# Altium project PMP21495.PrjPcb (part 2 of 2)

## Sheet PowerStage.SchDoc
size 431 x 279 mm; Date: Not shown in title block; ApprovedBy: Not shown in title block; CheckedBy: Not shown in title block; Author: Not shown in title block; CompanyName: Not shown in title block; Engineer: Not shown in title block; Organization: Not shown in title block; Address1: Not shown in title block; Address2: Not shown in title block; Address3: Not shown in title block; Address4: Not shown in title block; DocumentNumber: 1; Revision: Use project parameter SCH_Rev; SheetNumber: 1; SheetTotal: 2; PageSetup: Record=PageOptions¦CenterHorizontal=True¦CenterVertical=True¦PrintScale=1.00¦XCorrection=1.00¦YCorrection=1.00¦PrintKind=0¦BorderSize=5000000¦LeftOffset=0¦BottomOffset=0¦Orientation=2¦PaperLength=1000¦PaperWidth=1000¦Scale=100¦PaperSource=15¦PrintQuality=600¦MediaType=1¦DitherType=10¦PaperKind=Letter¦PrintScaleMode=1
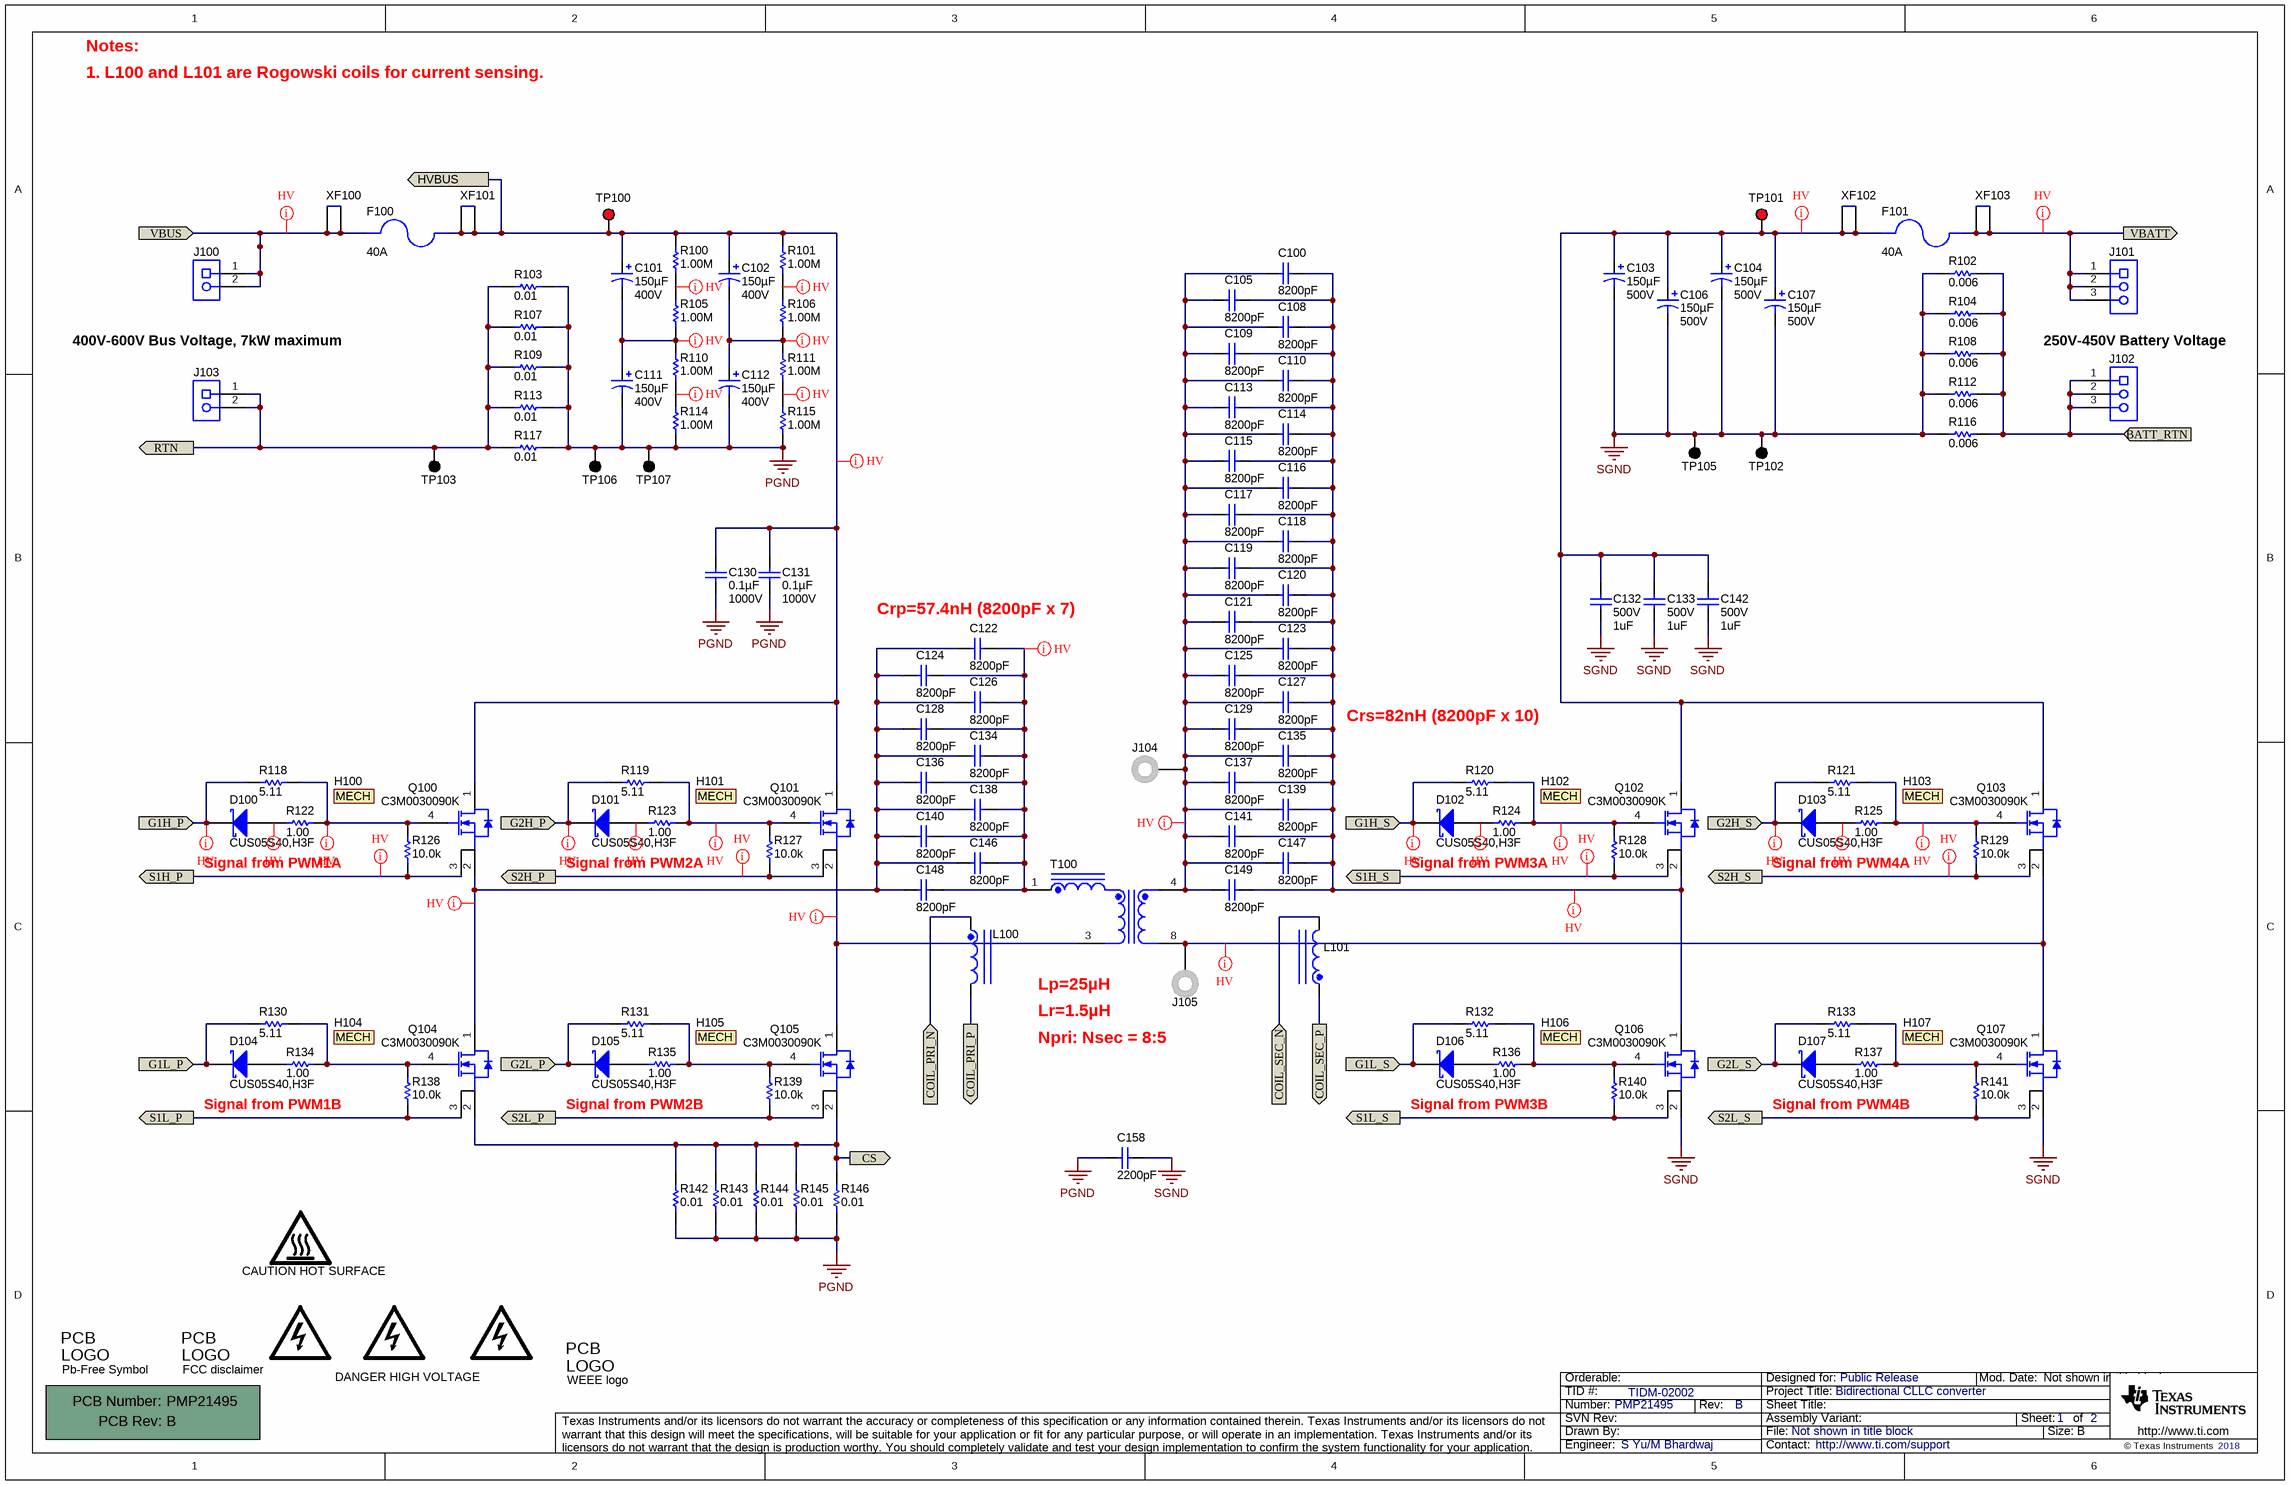
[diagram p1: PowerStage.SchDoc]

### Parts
!PCB100  Printed Circuit Board  (value not drawn)  (mechanical)
C100  ValueDisplayed: 8200pF  [1206_190]
C101  ValueDisplayed: 150µF  Value2: 400V  [FC_1600x4000]  (hidden comment: 400BXW150MEFC16X45)
C102  ValueDisplayed: 150µF  Value2: 400V  [FC_1600x4000]  (hidden comment: 400BXW150MEFC16X45)
C103  ValueDisplayed: 150µF  Value2: 500V  [Nichicon_2200x4500_Snap]  (hidden comment: 500MXG150MEFCSN22X55)
C104  ValueDisplayed: 150µF  Value2: 500V  [Nichicon_2200x4500_Snap]  (hidden comment: 500MXG150MEFCSN22X55)
C105  ValueDisplayed: 8200pF  [1206_190]
C106  ValueDisplayed: 150µF  Value2: 500V  [Nichicon_2200x4500_Snap]  (hidden comment: 500MXG150MEFCSN22X55)
C107  ValueDisplayed: 150µF  Value2: 500V  [Nichicon_2200x4500_Snap]  (hidden comment: 500MXG150MEFCSN22X55)
C108  ValueDisplayed: 8200pF  [1206_190]
C109  ValueDisplayed: 8200pF  [1206_190]
C110  ValueDisplayed: 8200pF  [1206_190]
C111  ValueDisplayed: 150µF  Value2: 400V  [FC_1600x4000]  (hidden comment: 400BXW150MEFC16X45)
C112  ValueDisplayed: 150µF  Value2: 400V  [FC_1600x4000]  (hidden comment: 400BXW150MEFC16X45)
C113  ValueDisplayed: 8200pF  [1206_190]
C114  ValueDisplayed: 8200pF  [1206_190]
C115  ValueDisplayed: 8200pF  [1206_190]
C116  ValueDisplayed: 8200pF  [1206_190]
C117  ValueDisplayed: 8200pF  [1206_190]
C118  ValueDisplayed: 8200pF  [1206_190]
C119  ValueDisplayed: 8200pF  [1206_190]
C120  ValueDisplayed: 8200pF  [1206_190]
C121  ValueDisplayed: 8200pF  [1206_190]
C122  ValueDisplayed: 8200pF  [1206_190]
C123  ValueDisplayed: 8200pF  [1206_190]
C124  ValueDisplayed: 8200pF  [1206_190]
C125  ValueDisplayed: 8200pF  [1206_190]
C126  ValueDisplayed: 8200pF  [1206_190]
C127  ValueDisplayed: 8200pF  [1206_190]
C128  ValueDisplayed: 8200pF  [1206_190]
C129  ValueDisplayed: 8200pF  [1206_190]
C130  ValueDisplayed: 0.1µF  Value2: 1000V  [1812_254]  (hidden comment: 1812Y1K00104KXT)
C131  ValueDisplayed: 0.1µF  Value2: 1000V  [1812_254]  (hidden comment: 1812Y1K00104KXT)
C132  VDC_V: 500V  ValueDisplayed: 1uF  [B58031I_1084x785x450]  (hidden comment: B58031I5105M002)
C133  VDC_V: 500V  ValueDisplayed: 1uF  [B58031I_1084x785x450]  (hidden comment: B58031I5105M002)
C134  ValueDisplayed: 8200pF  [1206_190]
C135  ValueDisplayed: 8200pF  [1206_190]
C136  ValueDisplayed: 8200pF  [1206_190]
C137  ValueDisplayed: 8200pF  [1206_190]
C138  ValueDisplayed: 8200pF  [1206_190]
C139  ValueDisplayed: 8200pF  [1206_190]
C140  ValueDisplayed: 8200pF  [1206_190]
C141  ValueDisplayed: 8200pF  [1206_190]
C142  VDC_V: 500V  ValueDisplayed: 1uF  [B58031I_1084x785x450]  (hidden comment: B58031I5105M002)
C146  ValueDisplayed: 8200pF  [1206_190]
C147  ValueDisplayed: 8200pF  [1206_190]
C148  ValueDisplayed: 8200pF  [1206_190]
C149  ValueDisplayed: 8200pF  [1206_190]
C158  ValueDisplayed: 2200pF  [CAPRD1000W60D900H1200]  (hidden comment: DE1E3KX222MA4BL01)
D100  CUS05S40,H3F  [SOD-323]
D101  CUS05S40,H3F  [SOD-323]
D102  CUS05S40,H3F  [SOD-323]
D103  CUS05S40,H3F  [SOD-323]
D104  CUS05S40,H3F  [SOD-323]
D105  CUS05S40,H3F  [SOD-323]
D106  CUS05S40,H3F  [SOD-323]
D107  CUS05S40,H3F  [SOD-323]
F100  Irating_A: 40A  (hidden comment: SC-40)  (mechanical)
F101  Irating_A: 40A  (hidden comment: SC-40)  (mechanical)
H100  (no value)  (mechanical)
H101  (no value)  (mechanical)
H102  (no value)  (mechanical)
H103  (no value)  (mechanical)
H104  (no value)  (mechanical)
H105  (no value)  (mechanical)
H106  (no value)  (mechanical)
H107  (no value)  (mechanical)
J100  282856-2  [TE_282856-2]  (value not drawn)
J101  282856-3  [TE_282856-3]  (value not drawn)
J102  282856-3  [TE_282856-3]  (value not drawn)
J103  282856-2  [TE_282856-2]  (value not drawn)
J104  575-4  [Keystone_575-4]  (value not drawn)
J105  575-4  [Keystone_575-4]  (value not drawn)
L100  RLTI-1310  [RLTI-1310]  (value not drawn)
L101  RLTI-1310  [RLTI-1310]  (value not drawn)
Logo2  Pb-Free Symbol  [Pb-Free_Overlay_Medium]  (no BOM)
Logo3  FCC disclaimer  [FCC_disclaimer]  (no BOM)
Logo4  WEEE logo  [WEEE_Minimum]  (no BOM)
LOGO100  CAUTION HOT SURFACE  [IEC_HotSurface_Medium]  (no BOM)
LOGO101  DANGER HIGH VOLTAGE  [IEC_HighVoltage_Medium]  (value not drawn)  (no BOM)
LOGO102  DANGER HIGH VOLTAGE  [IEC_HighVoltage_Medium]  (no BOM)
LOGO104  DANGER HIGH VOLTAGE  [IEC_HighVoltage_Medium]  (value not drawn)  (no BOM)
Q100  C3M0030090K  [TO-247-4]
Q101  C3M0030090K  [TO-247-4]
Q102  C3M0030090K  [TO-247-4]
Q103  C3M0030090K  [TO-247-4]
Q104  C3M0030090K  [TO-247-4]
Q105  C3M0030090K  [TO-247-4]
Q106  C3M0030090K  [TO-247-4]
Q107  C3M0030090K  [TO-247-4]
R100  ValueDisplayed: 1.00M  [1206]  (hidden comment: CRCW12061M00FKEA)
R101  ValueDisplayed: 1.00M  [1206]  (hidden comment: CRCW12061M00FKEA)
R102  ValueDisplayed: 0.006  [CSNL1206]  (hidden comment: PMR18EZPFU6L00)
R103  ValueDisplayed: 0.01  [1206]  (hidden comment: WSLP1206R0100FEA)
R104  ValueDisplayed: 0.006  [CSNL1206]  (hidden comment: PMR18EZPFU6L00)
R105  ValueDisplayed: 1.00M  [1206]  (hidden comment: CRCW12061M00FKEA)
R106  ValueDisplayed: 1.00M  [1206]  (hidden comment: CRCW12061M00FKEA)
R107  ValueDisplayed: 0.01  [1206]  (hidden comment: WSLP1206R0100FEA)
R108  ValueDisplayed: 0.006  [CSNL1206]  (hidden comment: PMR18EZPFU6L00)
R109  ValueDisplayed: 0.01  [1206]  (hidden comment: WSLP1206R0100FEA)
R110  ValueDisplayed: 1.00M  [1206]  (hidden comment: CRCW12061M00FKEA)
R111  ValueDisplayed: 1.00M  [1206]  (hidden comment: CRCW12061M00FKEA)
R112  ValueDisplayed: 0.006  [CSNL1206]  (hidden comment: PMR18EZPFU6L00)
R113  ValueDisplayed: 0.01  [1206]  (hidden comment: WSLP1206R0100FEA)
R114  ValueDisplayed: 1.00M  [1206]  (hidden comment: CRCW12061M00FKEA)
R115  ValueDisplayed: 1.00M  [1206]  (hidden comment: CRCW12061M00FKEA)
R116  ValueDisplayed: 0.006  [CSNL1206]  (hidden comment: PMR18EZPFU6L00)
R117  ValueDisplayed: 0.01  [1206]  (hidden comment: WSLP1206R0100FEA)
R118  ValueDisplayed: 5.11  [0603]  (hidden comment: CRCW06035R11FKEA)
R119  ValueDisplayed: 5.11  [0603]  (hidden comment: CRCW06035R11FKEA)
R120  ValueDisplayed: 5.11  [0603]  (hidden comment: CRCW06035R11FKEA)
R121  ValueDisplayed: 5.11  [0603]  (hidden comment: CRCW06035R11FKEA)
R122  ValueDisplayed: 1.00  [0603]  (hidden comment: RC0603FR-071RL)
R123  ValueDisplayed: 1.00  [0603]  (hidden comment: RC0603FR-071RL)
R124  ValueDisplayed: 1.00  [0603]  (hidden comment: RC0603FR-071RL)
R125  ValueDisplayed: 1.00  [0603]  (hidden comment: RC0603FR-071RL)
R126  ValueDisplayed: 10.0k  [0603]  (hidden comment: CRCW060310K0FKEA)
R127  ValueDisplayed: 10.0k  [0603]  (hidden comment: CRCW060310K0FKEA)
R128  ValueDisplayed: 10.0k  [0603]  (hidden comment: CRCW060310K0FKEA)
R129  ValueDisplayed: 10.0k  [0603]  (hidden comment: CRCW060310K0FKEA)
R130  ValueDisplayed: 5.11  [0603]  (hidden comment: CRCW06035R11FKEA)
R131  ValueDisplayed: 5.11  [0603]  (hidden comment: CRCW06035R11FKEA)
R132  ValueDisplayed: 5.11  [0603]  (hidden comment: CRCW06035R11FKEA)
R133  ValueDisplayed: 5.11  [0603]  (hidden comment: CRCW06035R11FKEA)
R134  ValueDisplayed: 1.00  [0603]  (hidden comment: RC0603FR-071RL)
R135  ValueDisplayed: 1.00  [0603]  (hidden comment: RC0603FR-071RL)
R136  ValueDisplayed: 1.00  [0603]  (hidden comment: RC0603FR-071RL)
R137  ValueDisplayed: 1.00  [0603]  (hidden comment: RC0603FR-071RL)
R138  ValueDisplayed: 10.0k  [0603]  (hidden comment: CRCW060310K0FKEA)
R139  ValueDisplayed: 10.0k  [0603]  (hidden comment: CRCW060310K0FKEA)
R140  ValueDisplayed: 10.0k  [0603]  (hidden comment: CRCW060310K0FKEA)
R141  ValueDisplayed: 10.0k  [0603]  (hidden comment: CRCW060310K0FKEA)
R142  ValueDisplayed: 0.01  [1206]  (hidden comment: WSLP1206R0100FEA)
R143  ValueDisplayed: 0.01  [1206]  (hidden comment: WSLP1206R0100FEA)
R144  ValueDisplayed: 0.01  [1206]  (hidden comment: WSLP1206R0100FEA)
R145  ValueDisplayed: 0.01  [1206]  (hidden comment: WSLP1206R0100FEA)
R146  ValueDisplayed: 0.01  [1206]  (hidden comment: WSLP1206R0100FEA)
T100  (no value)  [Payton_60518]
TP100  5000  [Keystone5000]  (value not drawn)
TP101  5000  [Keystone5000]  (value not drawn)
TP102  5001  [Keystone5001]  (value not drawn)
TP103  5001  [Keystone5001]  (value not drawn)
TP105  5001  [Keystone5001]  (value not drawn)
TP106  5001  [Keystone5001]  (value not drawn)
TP107  5001  [Keystone5001]  (value not drawn)
XF100  1A3400-10  [Eaton_1A3400-10]  (value not drawn)
XF101  1A3400-10  [Eaton_1A3400-10]  (value not drawn)
XF102  1A3400-10  [Eaton_1A3400-10]  (value not drawn)
XF103  1A3400-10  [Eaton_1A3400-10]  (value not drawn)

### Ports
BATT_RTN, COIL_PRI_N, COIL_PRI_P (out), COIL_SEC_N, COIL_SEC_P (out), CS (out), G1H_P (in), G1H_S (in), G1L_P (in), G1L_S (in), G2H_P (in), G2H_S (in), G2L_P (in), G2L_S (in), HVBUS, RTN (out), S1H_P, S1H_S, S1L_P, S1L_S, S2H_P, S2H_S, S2L_P, S2L_S, VBATT (out), VBUS (in)

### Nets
PGND: C111.2(-) C112.2(-) C130.2 C131.2 C158.2 R103.1 R107.1 R109.1 R113.1 R114.1 R115.1 R117.1 R142.1 R143.1 R144.1 R145.1 R146.1 TP106.1 TP107.1
SGND: C103.2(-) C104.2(-) C106.2(-) C107.2(-) C132.2 C133.2 C142.2 C158.1 Q106.2(S) Q107.2(S) R102.2 R104.2 R108.2 R112.2 R116.2 TP102.1 TP105.1
BATT_RTN: J102.1 J102.2 J102.3 R102.1 R104.1 R108.1 R112.1 R116.1 ; port BATT_RTN
COIL_PRI_N: L100.1 ; port COIL_PRI_N
COIL_PRI_P: L100.2 ; port COIL_PRI_P
COIL_SEC_N: L101.2 ; port COIL_SEC_N
COIL_SEC_P: L101.1 ; port COIL_SEC_P
CS: Q104.2(S) Q105.2(S) R142.2 R143.2 R144.2 R145.2 R146.2 ; port CS
G1H_P: D100.1(K) R118.1 ; port G1H_P
G1H_S: D102.1(K) R120.1 ; port G1H_S
G1L_P: D104.1(K) R130.1 ; port G1L_P
G1L_S: D106.1(K) R132.1 ; port G1L_S
G2H_P: D101.1(K) R119.1 ; port G2H_P
G2H_S: D103.1(K) R121.1 ; port G2H_S
G2L_P: D105.1(K) R131.1 ; port G2L_P
G2L_S: D107.1(K) R133.1 ; port G2L_S
HVBUS: C101.1(+) C102.1(+) C130.1 C131.1 Q100.1(D) Q101.1(D) R100.2 R101.2 TP100.1 XF101.1 XF101.2 ; port HVBUS
RTN: J103.1 J103.2 R103.2 R107.2 R109.2 R113.2 R117.2 TP103.1 ; port RTN
S1H_P: Q100.3(KS) R126.1 ; port S1H_P
S1H_S: Q102.3(KS) R128.1 ; port S1H_S
S1L_P: Q104.3(KS) R138.1 ; port S1L_P
S1L_S: Q106.3(KS) R140.1 ; port S1L_S
S2H_P: Q101.3(KS) R127.1 ; port S2H_P
S2H_S: Q103.3(KS) R129.1 ; port S2H_S
S2L_P: Q105.3(KS) R139.1 ; port S2L_P
S2L_S: Q107.3(KS) R141.1 ; port S2L_S
VBATT: J101.1 J101.2 J101.3 XF103.1 XF103.2 ; port VBATT
VBUS: J100.1 J100.2 XF100.1 XF100.2 ; port VBUS
NetC100_1: C100.1 C105.1 C108.1 C109.1 C110.1 C113.1 C114.1 C115.1 C116.1 C117.1 C118.1 C119.1 C120.1 C121.1 C123.1 C125.1 C127.1 C129.1 C135.1 C137.1 C139.1 C141.1 C147.1 C149.1 Q102.2(S) Q106.1(D)
NetC100_2: C100.2 C105.2 C108.2 C109.2 C110.2 C113.2 C114.2 C115.2 C116.2 C117.2 C118.2 C119.2 C120.2 C121.2 C123.2 C125.2 C127.2 C129.2 C135.2 C137.2 C139.2 C141.2 C147.2 C149.2 J104.1 T100.4
NetC101_2: C101.2(-) C111.1(+) R105.1 R110.2
NetC102_2: C102.2(-) C112.1(+) R106.1 R111.2
NetC103_1: C103.1(+) C104.1(+) C106.1(+) C107.1(+) C132.1 C133.1 C142.1 Q102.1(D) Q103.1(D) TP101.1 XF102.1 XF102.2
NetC122_1: C122.1 C124.1 C126.1 C128.1 C134.1 C136.1 C138.1 C140.1 C146.1 C148.1 T100.1
NetC122_2: C122.2 C124.2 C126.2 C128.2 C134.2 C136.2 C138.2 C140.2 C146.2 C148.2 Q100.2(S) Q104.1(D)
NetD100_2: D100.2(A) R122.1
NetD101_2: D101.2(A) R123.1
NetD102_2: D102.2(A) R124.1
NetD103_2: D103.2(A) R125.1
NetD104_2: D104.2(A) R134.1
NetD105_2: D105.2(A) R135.1
NetD106_2: D106.2(A) R136.1
NetD107_2: D107.2(A) R137.1
NetJ105_1: J105.1 Q103.2(S) Q107.1(D) T100.8
NetQ100_4: Q100.4(G) R118.2 R122.2 R126.2
NetQ101_2: Q101.2(S) Q105.1(D) T100.3
NetQ101_4: Q101.4(G) R119.2 R123.2 R127.2
NetQ102_4: Q102.4(G) R120.2 R124.2 R128.2
NetQ103_4: Q103.4(G) R121.2 R125.2 R129.2
NetQ104_4: Q104.4(G) R130.2 R134.2 R138.2
NetQ105_4: Q105.4(G) R131.2 R135.2 R139.2
NetQ106_4: Q106.4(G) R132.2 R136.2 R140.2
NetQ107_4: Q107.4(G) R133.2 R137.2 R141.2
NetR100_1: R100.1 R105.2
NetR101_1: R101.1 R106.2
NetR110_1: R110.1 R114.2
NetR111_1: R111.1 R115.2

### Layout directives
net class HV: G1H_P, G1H_S, G2H_P, G2H_S, HVBUS, NetC100_1, NetC100_2, NetC101_2, NetC102_2, NetC103_1, NetC122_1, NetC122_2, NetD100_2, NetD101_2, NetD102_2, NetD103_2, NetJ105_1, NetQ100_4, NetQ101_2, NetQ101_4, NetQ102_4, NetQ103_4, NetR100_1, NetR101_1, NetR110_1, NetR111_1, S1H_P, S1H_S, S2H_P, S2H_S, VBATT, VBUS

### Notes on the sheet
- Notes:
- 1. L100 and L101 are Rogowski coils for current sensing.
- 400V-600V Bus Voltage, 7kW maximum
- 250V-450V Battery Voltage
- (near C122) Crp=57.4nH (8200pF x 7)
- Crs=82nH (8200pF x 10)
- Signal from PWM1A
- Signal from PWM2A
- Signal from PWM3A
- Signal from PWM4A
- (near T100) Lp=25µH
- Lr=1.5µH
- Npri: Nsec = 8:5
- Signal from PWM1B
- Signal from PWM2B
- Signal from PWM3B
- Signal from PWM4B

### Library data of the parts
!PCB100 = CMP-0003618-2: Manufacturer: Any; PartNumber: PMP21495
C100 C105 C108-C110 C113-C129 C134-C141 C146-C149 = CMP-0008795-2: CAP CER 8200PF 630V NP0 1206; Manufacturer: TDK; PartNumber: CGA5L4NP02J822J160AA; TaMin_C: -55°C; Polarized: N; TempCo: C0G; SizeAreaWB_mm2: 10.92; Value1: Unknown; U/M: EA; TaMax_C: 125°C; Tolerance_%: 5%; SizeZ_mm: 1.9; SizeX_mm: 3.2; SizeY_mm: 1.6; Cap_Case: 1206; SizeArea_mm2: 5.12; CompType: Capacitor; AEC Qualified: Y; Cap_F: 100nF; AEC Grade: 1; AEC Category: Q200
C101 C102 C111 C112 = EEU-FC2A471: CAP ALUM 150UF 20% 400V RADIAL; Manufacturer: Rubycon; Polarized: Y; CompType: Capacitor; U/M: EA; Tolerance_%: 20; VDC_V: 400; ESR_ohm: 0.047; IRMS_A: 1.92; TaMin_C: -55; TaMax_C: 105; Cap_Case: 16x40mm; SizeAreaWB_mm2: 324; SizeArea_mm2: 256; SizeX_mm: 16; SizeZ_mm: 42; AEC Category: Q200; AEC Grade: 2; Green_Lifecycle: Active; Green_REACh: Passed
C103 C104 C106 C107 = LLS2G221MELZ: CAP ALUM 150UF 20% 500V SNAP; Manufacturer: Rubycon; Polarized: Y; CompType: Capacitor; U/M: EA; Cap_F: 0.00022; Tolerance_%: 20; VDC_V: 500; IRMS_A: 1.58; Cap_Case: 22x45mm; SizeAreaWB_mm2: 576; SizeArea_mm2: 484; SizeX_mm: 22; SizeZ_mm: 47; AEC Category: Q200; AEC Qualified: N
C130 = C1812W104KDRACTU: CAP, CERM, 0.1 µF, 1000 V,+/- 10%, X7R, 1812; Manufacturer: Knowles Syfer; Polarized: N; CompType: Capacitor; Value: 0.1uF; U/M: EA; Cap_F: 0.0000001; Tolerance_%: 10; VDC_V: 1000; TaMin_C: -55; TaMax_C: 125; Cap_Case: 1812; SizeArea_mm2: 14.4; SizeAreaWB_mm2: 23.1; SizeX_mm: 4.5; SizeY_mm: 3.2; SizeZ_mm: 2.54; AEC Category: Q200; Green_Lifecycle: Active; Green_REACh: Passed
C131 = C1812W104KDRACTU: CAP CER 0.1UF 1KV X7R 1812; Manufacturer: Knowles Syfer; Polarized: N; CompType: Capacitor; U/M: EA; Cap_F: 0.0000001; Tolerance_%: 10; VDC_V: 1000; TaMin_C: -55; TaMax_C: 125; Cap_Case: 1812; SizeArea_mm2: 14.4; SizeAreaWB_mm2: 23.1; SizeX_mm: 4.5; SizeY_mm: 3.2; SizeZ_mm: 2.54; AEC Category: Q200; Green_Lifecycle: Active; Green_REACh: Passed
C132 C133 C142 = CMP-0009311-2: CAP, CERM, 1 uF, 500 V, +/- 20%, B58031, AEC-Q200 Grade 0, 6.84x7.85mm; Manufacturer: TDK; PartNumber: B58031I5105M062; TaMin_C: -40°C; Polarized: N; SizeAreaWB_mm2: 126.474; Value1: Unknown; U/M: EA; Value: 1uF; TaMax_C: 150°C; SizeZ_mm: 4.5; SizeX_mm: 10.84; SizeY_mm: 7.85; Cap_Case: 10.84x7.85x4.5mm; SizeArea_mm2: 85.094; CompType: Capacitor; AEC Qualified: Y; Cap_F: 1µF; IRMS_A: 7.5A; AEC Grade: 0; AEC Category: Q200
C158 = DE1E3KX222MA4BL01: CAP, CERM, 2200 pF, 250 V, +/- 20%, E, Cap, 7x12x9 mm; Manufacturer: MuRata; Polarized: N; CompType: Capacitor; Value: 2200pF; U/M: EA; Cap_F: 0.0000000022; Tolerance_%: 20; Value1: Unknown; VDC_V: 250; Value2: 250V; TaMin_C: -25; TaMax_C: 85
D100-D107 = CUS05S40,H3F: Diode, Schottky, 40 V, 0.5 A, SOD-323; Manufacturer: Toshiba; U/M: EA; Vf_V: 0.6; Value: 40V; Value1: 0.5A; Value2: 0.6V; Io_A: 0.5; Vr_V: 40; TJmax_C: 125; SizeAreaWB_mm2: 8.695; SizeArea_mm2: 3.645; SizeX_mm: 2.7; SizeY_mm: 1.35; SizeZ_mm: 1; AEC Category: Q101; AEC Qualified: N; Green_Lifecycle: Not Set; Green_REACh: Incomplete
F100 F101 = CMP-0082087-1: Fuse, 40 A, 480 VAC, 300 VDC, Holder; Manufacturer: Eaton; Fuse Speed: Slow; Fuse Technology: Cartridge; VAC_V: 480V; Interrupt_AC: 100kA; VDC_V: 300V; Interrupt_DC: 10kA
H100-H107 = CMP-0082086-1: THERM PAD 21.84MMX18.8MM PINK; Manufacturer: Bergquist; PartNumber: SP900S-0.009-00-90; CompType: Thermal Pad
J100 J103 = CMP-0054978-1: Therminal Block, 5 mm, 2-pole, Tin, TH; Manufacturer: TE Connectivity; CT: TRUE; CompType: Terminal Block; CNHeader: FALSE
J101 J102 = CMP-0054983-1: Receptacle, 3x1, 5mm, R/A, TH; Manufacturer: TE Connectivity; CNHeader: FALSE; Current_A: 24A; Gender: Female; Voltage_V: 300V; CompType: Terminal Block; Row_Count: 1; Pitch_mm: 5; ContactFinish: Tin; CT: TRUE; Cert_UL: Y
J104 J105 = CMP-0055165-2: Standard Banana Jack, Uninsulated, 5.5mm; Manufacturer: Keystone; CT: TRUE; Green_REACh: Passed; CNHeader: FALSE; Green_Lifecycle: Active
L100 L101 = CMP-0086080-1: Inductor, Toroid, 7 µH, 1.155 ohm, TH; Manufacturer: Renco Electronics; SizeZ_mm: 18.669; SizeAreaWB_mm2: 135.836668; SizeX_mm: 4.572; AEC Qualified: N; AEC Category: Q200; Ind_H: 7µH; DCR_ohm: 1.155; Value: 7uH; Value2: A; SizeArea_mm2: 85.354668
Logo2 = CMP-0074839-1: SymbolCreator: a0412235; Library Reference: Logo
Logo3 = CMP-0074847-1: FCC_disclaimer; Library Reference: Logo
Logo4 = CMP-0074769-1
LOGO100 = IEC_HotSurface: IEC 61010-1 Hot Surface Warning; SymbolCreator: a0412235
LOGO101 LOGO102 LOGO104 = IEC_HighVoltage: IEC 61010-1 High Voltage Warning; SymbolCreator: a0412235
Q100-Q107 = CMP-0067575-2: ZFET 900V, 30 MOHM, G3 SIC MOSFE; Manufacturer: Cree; Alternate Manufacturer: None; CompType: MOSFET; AEC Qualified: N; AEC Category: Q101; U/M: EA
R100 R101 R105 R106 R110 R111 R114 R115 = CRCW12061M00FKEA: RES, 1.00 M, 1%, 0.25 W, 1206; Manufacturer: Vishay-Dale; CompType: Resistor; Value: 1.00Meg; Res_ohm: 1000000; Value_Code: 1M00; Tolerance_%: 1; Power_W: 0.25; Value2: 0.25W; VDC_V: 200; TempCo: 100 ppm/C; SizeArea_mm2: 5.12; SizeX_mm: 3.2; SizeY_mm: 1.6; SizeZ_mm: 1.35; EIA_Code: E96; U/M: EA; AEC Category: Q200; Green_Lifecycle: Active; Green_REACh: Passed
R102 R104 R108 R112 R116 = CSNL1206FT5L00: RES 0.006 OHM 1% 1W 1206; Manufacturer: Rohm Semiconductor; CompType: Resistor; Value: 0.006; Tolerance_%: 1; TempCo: 50 ppm/C; SizeArea_mm2: 5.12; SizeX_mm: 3.2; SizeY_mm: 1.6; SizeZ_mm: 0.9; EIA_Code: E96; U/M: EA; AEC Category: Q200; AEC Qualified: N
R103 R107 R109 R113 R117 R142-R146 = CMP-0018570-2: RES, 0.01, 1%, 1 W, 1206; Manufacturer: Vishay-Dale; Power_W: 1W; TempCo: 75 ppm/C; Value_Code: R010; U/M: EA; Value: 0.01; EIA_Code: E96; SizeX_mm: 3.2; SizeY_mm: 1.6; SizeZ_mm: 1.35; SizeArea_mm2: 5.12; CompType: Resistor; AEC Category: Q200
R118-R121 R130-R133 = CRCW06035R11FKEA: RES, 5.11, 1%, 0.1 W, 0603; Manufacturer: Vishay-Dale; CompType: Resistor; Value: 5.11; Value_Code: 5R11; Tolerance_%: 1; Power_W: 0.1; Value2: 0.1W; VDC_V: 75; TempCo: 100 ppm/C; SizeArea_mm2: 1.28; SizeX_mm: 1.6; SizeY_mm: 0.8; EIA_Code: E96; U/M: EA; AEC Category: Q200; Green_Lifecycle: Active; Green_REACh: Passed
R122-R125 R134-R137 = RC0603FR-071RL: RES, 1.00, 1%, 0.1 W, 0603; Manufacturer: Yageo America; CompType: Resistor; Value: 1.00; Res_ohm: 1; Value_Code: 1R00; Power_W: 0.1; Value2: 0.1W; VDC_V: 150; TempCo: 200 ppm/C; SizeArea_mm2: 1.28; SizeX_mm: 1.6; SizeY_mm: 0.8; EIA_Code: E96; U/M: EA; AEC Category: Q200; Green_Lifecycle: Active; Green_REACh: Passed
R126-R129 R138-R141 = CRCW060310K0FKEA: RES, 10.0 k, 1%, 0.1 W, 0603; Manufacturer: Vishay-Dale; CompType: Resistor; Value: 10.0k; Res_ohm: 10000; Value_Code: 10k0; Tolerance_%: 1; Power_W: 0.1; Value2: 0.1W; VDC_V: 75; TempCo: 100 ppm/C; SizeArea_mm2: 1.28; SizeX_mm: 1.6; SizeY_mm: 0.8; EIA_Code: E96; U/M: EA; AEC Category: Q200; Green_Lifecycle: Active; Green_REACh: Passed
T100 = CMP-0081898-1: Transformer, 25 uH, TH; Manufacturer: Payton; PartNumber: 60814; SizeAreaWB_mm2: 13800; Value: 25uH; Lp: 25; SizeZ_mm: 60; SizeX_mm: 148; SizeY_mm: 90; Ns1toNp: 0.625; SizeArea_mm2: 13320; Ind_H: 25µH; AEC Qualified: N; AEC Category: Q200
TP100 TP101 = 5000: Test Point, Miniature, Red, TH; Manufacturer: Keystone; CompType: Test Point Loop; ContactFinish: Silver; Green_Lifecycle: Active; Green_REACh: Passed
TP102 TP103 TP105-TP107 = 5001: Test Point, Miniature, Black, TH; Manufacturer: Keystone; CompType: Test Point Loop; ContactFinish: Silver; Green_Lifecycle: Active; Green_REACh: Passed
XF100-XF103 = CMP-0082116-2: FUSE CLIP CARTRIDGE 30A PCB; PartNumber: BK/1A3400-10; Manufacturer: Eaton; CompType: Fuse Holder

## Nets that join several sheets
PGND: Controller (85 pins), PowerStage (19 pins)
SGND: Controller (17 pins), PowerStage (17 pins)
BATT_RTN: Controller (R230.1), PowerStage (8 pins)
COIL_PRI_N: Controller (5 pins), PowerStage (L100.1)
COIL_PRI_P: Controller (R262.1), PowerStage (L100.2)
COIL_SEC_N: Controller (5 pins), PowerStage (L101.2)
COIL_SEC_P: Controller (R257.1), PowerStage (L101.1)
CS: Controller (R213.2), PowerStage (7 pins)
G1H_P: Controller (TP204.1), PowerStage (D100.1 R118.1)
G1H_S: Controller (TP212.1), PowerStage (D102.1 R120.1)
G1L_P: Controller (TP200.1), PowerStage (D104.1 R130.1)
G1L_S: Controller (TP208.1), PowerStage (D106.1 R132.1)
G2H_P: Controller (TP205.1), PowerStage (D101.1 R119.1)
G2H_S: Controller (TP213.1), PowerStage (D103.1 R121.1)
G2L_P: Controller (TP201.1), PowerStage (D105.1 R131.1)
G2L_S: Controller (TP209.1), PowerStage (D107.1 R133.1)
HVBUS: Controller (R202.2), PowerStage (11 pins)
RTN: Controller (R203.1), PowerStage (8 pins)
S1H_P: Controller (TP206.1), PowerStage (Q100.3 R126.1)
S1H_S: Controller (TP214.1), PowerStage (Q102.3 R128.1)
S1L_P: Controller (TP202.1), PowerStage (Q104.3 R138.1)
S1L_S: Controller (TP210.1), PowerStage (Q106.3 R140.1)
S2H_P: Controller (TP207.1), PowerStage (Q101.3 R127.1)
S2H_S: Controller (TP215.1), PowerStage (Q103.3 R129.1)
S2L_P: Controller (TP203.1), PowerStage (Q105.3 R139.1)
S2L_S: Controller (TP211.1), PowerStage (Q107.3 R141.1)
VBATT: Controller (J206.1 R237.2), PowerStage (5 pins)

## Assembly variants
001: not fitted C100 C105 C108 C109 C110 C113 C114 C115 C116 C117 C118 C128 C141 C146 C147 C148 C149 C208 C215 C216 C217 C221 C228 C229 C232 C244 C246 C250 C254 J104 J105 J206 J209 R208 R217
